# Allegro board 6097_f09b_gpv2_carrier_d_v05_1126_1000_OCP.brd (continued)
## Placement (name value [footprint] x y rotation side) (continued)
C584  10UF  [C0402]  178.01 81.03 270 bottom
C585  10UF  [C0402]  176.99 81.03 90 bottom
C586  10UF  [C0402]  183.64 87.53 0 bottom
C587  100UF  [C0805_H61]  196.55 47.85 180 top
C588  100UF  [C0805_H61]  191.64 99.42 270 bottom
C589  100UF  [C0805_H61]  195.7 48.81 180 bottom
C590  100UF  [C0805_H61]  193.52 99.42 270 bottom
C591  100UF  [C0805_H61]  197.82 41.91 270 top
C592  0.1UF  [C0201]  198.85 82.38 0 bottom
C593  0.1UF  [C0201]  189.59 84.68 180 bottom
C594  0.1UF  [C0201]  197.57 87.12 180 bottom
C595  0.1UF  [C0201]  197.96 88.83 270 bottom
C596  0.1UF  [C0201]  191.34 82.93 270 bottom
C597  0.1UF  [C0201]  197.03 89.02 90 bottom
C598  0.1UF  [C0201]  197.91 72.9 90 bottom
C599  0.1UF  [C0201]  197.61 74.04 180 bottom
C600  0.1UF  [C0201]  192.74 74.42 0 bottom
C601  0.1UF  [C0201]  195.62 72.14 270 bottom
C602  0.1UF  [C0201]  199.54 70 0 bottom
C603  0.1UF  [C0201]  197.9 76.83 90 bottom
C604  0.1UF  [C0201]  196.11 89.02 90 bottom
C605  0.1UF  [C0201]  192.71 86.79 0 bottom
C606  0.1UF  [C0201]  189.69 77.98 270 bottom
C607  0.1UF  [C0201]  194.66 82.3 180 bottom
C609  0.1UF  [C0201]  196.27 79.48 270 bottom
C610  0.1UF  [C0201]  191.05 80.9 90 bottom
C611  0.1UF  [C0201]  192.61 81.03 270 bottom
C612  0.1UF  [C0201]  197.38 79.98 270 bottom
C613  4.7UF  [C0402]  199.6 87.89 0 bottom
C614  100UF  [C0805_H61]  203.62 82.89 0 bottom
C615  4.7UF  [C0402]  199.6 89.66 0 bottom
C616  4.7UF  [C0402]  199.55 84.42 0 bottom
C617  4.7UF  [C0402]  199.6 86.36 0 bottom
C618  0.1UF  [C0201]  174.59 83.56 0 bottom
C619  0.1UF  [C0201]  174.59 76.56 0 bottom
C620  0.1UF  [C0201]  172.65 84.51 0 bottom
C621  0.1UF  [C0201]  170.59 83.56 0 bottom
C622  0.1UF  [C0201]  169.18 81.01 90 bottom
C623  0.1UF  [C0201]  170.16 81.01 90 bottom
C624  0.1UF  [C0201]  168.22 81.01 90 bottom
C625  0.1UF  [C0201]  172.66 83.59 180 bottom
C626  0.1UF  [C0201]  172.13 81.01 270 bottom
C627  0.1UF  [C0201]  171.59 76.49 0 bottom
C628  0.1UF  [C0201]  170.59 86.49 0 bottom
C629  0.1UF  [C0201]  171.12 81.01 90 bottom
C630  0.1UF  [C0201]  173.15 81.01 90 bottom
C631  0.1UF  [C0201]  170.59 84.49 0 bottom
C632  0.1UF  [C0201]  172.7 86.36 0 bottom
C633  0.1UF  [C0201]  171.59 75.56 0 bottom
C634  0.1UF  [C0201]  172.7 85.42 180 bottom
C635  0.1UF  [C0201]  170.59 85.56 0 bottom
C636  0.1UF  [C0201]  174.59 84.49 0 bottom
C637  0.1UF  [C0201]  174.17 81.01 270 bottom
C638  0.1UF  [C0201]  174.59 74.57 0 bottom
C639  0.1UF  [C0201]  171.59 78.49 0 bottom
C640  0.1UF  [C0201]  167.27 81.01 90 bottom
C641  0.1UF  [C0201]  174.59 77.49 0 bottom
C642  0.1UF  [C0201]  175.16 81.01 90 bottom
C643  0.1UF  [C0201]  174.59 75.49 0 bottom
C644  0.1UF  [C0201]  171.59 77.56 0 bottom
C645  4.7UF  [C0402]  163.22 76.66 180 bottom
C646  4.7UF  [C0402]  163.27 81.96 180 bottom
C647  4.7UF  [C0402]  163.27 80.94 180 bottom
C648  4.7UF  [C0402]  163.27 79.93 180 bottom
C649  4.7UF  [C0402]  163.27 78.91 180 bottom
C650  4.7UF  [C0402]  163.22 77.77 180 bottom
C651  0.1UF  [C0201]  183.62 72.19 180 bottom
C652  0.1UF  [C0201]  188.87 81.15 270 bottom
C653  0.1UF  [C0201]  183.6 89.49 180 bottom
C654  0.1UF  [C0201]  176.59 71.49 0 bottom
C655  100UF  [C0805_H61]  202.45 86.75 180 bottom
C656  0.1UF  [C0201]  176.59 89.56 0 bottom
C657  0.1UF  [C0201]  183.57 88.55 180 bottom
C658  0.1UF  [C0201]  183.62 71.25 180 bottom
C659  0.1UF  [C0201]  176.59 90.49 0 bottom
C660  0.1UF  [C0201]  176.59 70.57 0 bottom
C661  0.1UF  [C0201]  189.81 81.15 270 bottom
C662  0.1UF  [C0201]  171.61 71.98 0 bottom
C663  0.1UF  [C0201]  171.61 71.07 0 bottom
C664  0.1UF  [C0201]  171.61 70.15 0 bottom
C665  0.1UF  [C0201]  188.04 92.1 270 bottom
C666  0.1UF  [C0201]  193.32 92.05 270 bottom
C667  4.7UF  [C0402]  183.82 93.62 90 bottom
C668  4.7UF  [C0402]  183.57 91.54 180 bottom
C669  4.7UF  [C0402]  183.57 90.5 180 bottom
C670  4.7UF  [C0402]  196.68 94.19 90 bottom
C671  4.7UF  [C0402]  192.53 94.21 90 bottom
C672  4.7UF  [C0402]  194.59 94.21 90 bottom
C673  4.7UF  [C0402]  197.87 91.95 270 bottom
C674  4.7UF  [C0402]  190.6 94.21 90 bottom
C675  0.1UF  [C0201]  185.59 72.48 0 bottom
C676  0.1UF  [C0201]  191.27 91.95 270 bottom
C677  0.1UF  [C0201]  171.58 90.75 0 bottom
C678  0.1UF  [C0201]  177.39 72.77 0 bottom
C679  0.1UF  [C0201]  183.79 67.51 270 bottom
C680  0.1UF  [C0201]  185.59 71.55 0 bottom
C681  0.1UF  [C0201]  177.59 87.56 0 bottom
C682  0.1UF  [C0201]  171.61 72.89 0 bottom
C683  0.1UF  [C0201]  183.59 69.95 180 bottom
C684  0.1UF  [C0201]  171.61 73.81 0 bottom
C685  0.1UF  [C0201]  171.61 69.24 0 bottom
C686  0.1UF  [C0201]  182.29 68.82 90 bottom
C687  0.1UF  [C0201]  190.32 68.92 90 bottom
C688  0.1UF  [C0201]  179.17 68.82 90 bottom
C689  0.1UF  [C0201]  188.42 68.99 90 bottom
C690  0.1UF  [C0201]  187.48 68.99 90 bottom
C691  0.1UF  [C0201]  186.54 68.99 90 bottom
C692  0.1UF  [C0201]  185.6 68.99 90 bottom
C693  0.1UF  [C0201]  181.24 68.82 90 bottom
C694  0.1UF  [C0201]  180.21 68.82 90 bottom
C715  0.1UF  [C0201]  183.57 69.01 180 bottom
C716  0.1UF  [C0201]  196.05 67.95 270 bottom
C717  0.1UF  [C0201]  193.12 67.99 270 bottom
C718  0.1UF  [C0201]  195.14 67.92 270 bottom
C719  0.1UF  [C0201]  177.34 68.94 90 bottom
C720  0.1UF  [C0201]  176.33 68.91 90 bottom
C721  0.1UF  [C0201]  194.95 91.95 270 bottom
C722  0.1UF  [C0201]  175.29 68.91 90 bottom
C723  0.1UF  [C0201]  174.22 68.88 90 bottom
C724  0.1UF  [C0201]  173.15 68.88 90 bottom
C728  0.1UF  [C0201]  171.58 89.71 0 bottom
C729  0.1UF  [C0201]  171.55 88.57 0 bottom
C730  0.1UF  [C0201]  171.55 87.48 0 bottom
C732  0.1UF  [C0201]  190.25 90.06 270 bottom
C733  0.1UF  [C0201]  181.17 92.06 270 bottom
C734  0.1UF  [C0201]  180.01 92.06 270 bottom
C749  4.7UF  [C0402]  175.13 92.05 270 bottom
C750  4.7UF  [C0402]  173.02 92.02 270 bottom
C751  4.7UF  [C0402]  177.11 92.02 270 bottom
C752  4.7UF  [C0402]  186.97 92 270 bottom
C759  100NF  [C0402]  67.84 65.25 270 bottom
C760  1UF  [C0402]  66.83 65.25 270 bottom
C761  100NF  [C0402]  65.13 65.3 270 bottom
C762  1UF  [C0402]  64.11 65.3 270 bottom
C765  100NF  [C0402]  190.62 144.68 0 top
C769  100NF  [C0402]  59.97 57.81 0 bottom
C770  10UF  [C0402]  69.11 67.67 180 bottom
C771  100NF  [C0402]  63.7 57.2 90 bottom
C772  100NF  [C0402]  59.97 60.71 0 bottom
C773  100NF  [C0402]  67.97 57.68 180 bottom
C774  100NF  [C0402]  67.97 60.73 180 bottom
C775  100NF  [C0402]  67.97 61.75 180 bottom
C776  100NF  [C0402]  59.97 61.72 0 bottom
C806  1UF  [C0402]  76.66 26.09 0 top
C875  0.22UF  [C0402]  172.38 103.28 90 top
C876  0.22UF  [C0402]  171.3 103.27 90 top
C877  0.22UF  [C0402]  170.29 103.27 90 top
C878  0.22UF  [C0402]  160.29 100.25 180 top
C879  0.22UF  [C0402]  160.29 99.23 180 top
C880  0.22UF  [C0402]  190.73 103.13 90 bottom
C881  0.22UF  [C0402]  189.71 103.13 90 bottom
C882  0.22UF  [C0402]  189.14 105.14 90 bottom
C883  0.22UF  [C0402]  188.12 105.14 90 bottom
C884  0.22UF  [C0402]  187.49 103.18 90 bottom
C885  0.22UF  [C0402]  186.47 103.18 90 bottom
C886  0.22UF  [C0402]  185.76 105.1 90 bottom
C887  0.22UF  [C0402]  184.75 105.1 90 bottom
C888  0.22UF  [C0402]  183.98 101.55 90 bottom
C889  0.22UF  [C0402]  182.96 101.55 90 bottom
C890  0.22UF  [C0402]  181.49 102.84 90 bottom
C891  0.22UF  [C0402]  180.47 102.84 90 bottom
C892  0.22UF  [C0402]  178.97 104.98 90 bottom
C893  0.22UF  [C0402]  177.96 104.98 90 bottom
C894  0.22UF  [C0402]  175.18 103.72 90 bottom
C895  0.22UF  [C0402]  174.17 103.72 90 bottom
C896  0.22UF  [C0402]  184.22 103.38 90 top
C897  0.22UF  [C0402]  183.21 103.38 90 top
C898  0.22UF  [C0402]  182.01 103.36 90 top
C899  0.22UF  [C0402]  181 103.36 90 top
C900  0.22UF  [C0402]  179.78 103.38 90 top
C901  0.22UF  [C0402]  178.77 103.38 90 top
C902  0.22UF  [C0402]  177.55 103.34 90 top
C903  0.22UF  [C0402]  176.54 103.34 90 top
C904  0.22UF  [C0402]  175.48 103.3 90 top
C905  0.22UF  [C0402]  174.46 103.3 90 top
C906  0.22UF  [C0402]  173.4 103.28 90 top
C909  100NF  [C0402]  65.5 20.99 90 top
C910  100NF  [C0402]  66.52 20.99 90 top
C912  0.01UF  [C0402]  202.72 76.02 0 bottom
C913  0.01UF  [C0402]  202.72 75 0 bottom
C948  10UF  [C0805_H61]  194.05 3.43 0 bottom
C949  100NF  [C0402]  193.6 4.89 0 bottom
C950  100NF  [C0402]  183.92 119.48 0 top
C951  0.01UF  [C0402]  183.92 118.47 0 top
C952  100NF  [C0402]  89.2 39 180 top
C953  100NF  [C0402]  122.42 38.25 0 bottom
C954  12PF  [C0402]  112.3 40.43 90 top
C955  12PF  [C0402]  112.32 36.75 270 top
C959  1UF  [C0402]  122.42 39.3 180 bottom
C960  1UF  [C0402]  119.22 36.09 90 bottom
C961  1UF  [C0402]  118.17 36.04 90 bottom
C964  1UF  [C0402]  115.37 41.22 180 top
C965  1UF  [C0402]  122.42 37.19 180 bottom
C966  1UF  [C0402]  121.6 35.79 90 bottom
C967  1UF  [C0402]  120.54 36.04 90 bottom
C968  1UF  [C0402]  119.95 44.15 90 top
C969  22UF  [C0805_H61]  124.36 34.37 0 top
C970  0.01UF  [C0402]  121.95 33.53 270 top
C971  0.01UF  [C0402]  120.93 33.53 270 top
C972  1UF  [C0402]  115.67 37.47 270 top
C973  1UF  [C0402]  116.48 33.53 270 top
C974  1UF  [C0402]  117.5 33.53 270 top
C975  100NF  [C0402]  68.66 26.97 0 top
C1010  0.22UF  [C0402]  151.68 58.85 180 top
C1011  0.22UF  [C0402]  153.51 58.51 180 top
C1012  0.22UF  [C0402]  153.51 57.49 180 top
C1013  0.22UF  [C0402]  151.69 57.18 180 top
C1014  0.22UF  [C0402]  151.69 56.16 180 top
C1015  0.22UF  [C0402]  153.51 77.43 180 top
C1016  0.22UF  [C0402]  153.48 76.36 180 top
C1017  0.22UF  [C0402]  151.68 76.09 180 top
C1018  0.22UF  [C0402]  151.68 75.07 180 top
C1019  0.22UF  [C0402]  153.51 74.73 180 top
C1020  0.22UF  [C0402]  153.51 73.71 180 top
C1021  0.22UF  [C0402]  151.68 73.38 180 top
C1022  0.22UF  [C0402]  151.68 72.37 180 top
C1023  0.22UF  [C0402]  153.51 72.02 180 top
C1024  0.22UF  [C0402]  153.51 71.01 180 top
C1025  0.22UF  [C0402]  151.68 70.68 180 top
C1026  0.22UF  [C0402]  151.68 69.67 180 top
C1027  0.22UF  [C0402]  153.51 69.32 180 top
C1028  0.22UF  [C0402]  153.51 68.3 180 top
C1029  0.22UF  [C0402]  151.68 67.98 180 top
C1030  0.22UF  [C0402]  151.68 66.96 180 top
C1031  0.22UF  [C0402]  153.51 66.62 180 top
C1032  0.22UF  [C0402]  153.51 65.6 180 top
C1033  0.22UF  [C0402]  151.68 65.27 180 top
C1034  0.22UF  [C0402]  151.68 64.26 180 top
C1035  0.22UF  [C0402]  153.51 63.91 180 top
C1036  0.22UF  [C0402]  153.51 62.9 180 top
C1037  0.22UF  [C0402]  151.68 62.57 180 top
C1038  0.22UF  [C0402]  151.68 61.56 180 top
C1039  0.22UF  [C0402]  153.51 61.21 180 top
C1040  0.22UF  [C0402]  153.51 60.19 180 top
C1041  0.22UF  [C0402]  151.68 59.87 180 top
C1058  0.22UF  [C0402]  158.51 55.35 270 top
C1059  0.22UF  [C0402]  159.53 55.35 270 top
C1060  0.22UF  [C0402]  160.67 55.3 270 top
C1061  0.22UF  [C0402]  161.69 55.3 270 top
C1062  0.22UF  [C0402]  162.81 55.33 270 top
C1063  0.22UF  [C0402]  163.82 55.33 270 top
C1064  0.22UF  [C0402]  172.03 55.76 270 top
C1065  0.22UF  [C0402]  173.04 55.76 270 top
C1066  0.22UF  [C0402]  174.16 55.76 270 top
C1067  0.22UF  [C0402]  175.18 55.76 270 top
C1068  0.22UF  [C0402]  176.37 55.76 270 top
C1069  0.22UF  [C0402]  177.39 55.76 270 top
C1070  0.22UF  [C0402]  178.48 55.76 270 top
C1071  0.22UF  [C0402]  179.49 55.76 270 top
C1072  0.22UF  [C0402]  156.35 55.35 270 top
C1073  0.22UF  [C0402]  157.37 55.35 270 top
C1074  100NF  [C0402]  183.57 132.73 0 bottom
C1075  100NF  [C0402]  183.65 136.57 180 bottom
C1078  100NF  [C0402]  130.48 42.88 180 bottom
C1079  100NF  [C0402]  139.34 43 0 bottom
C1082  100NF  [C0402]  181.84 124.04 0 bottom
C1083  100NF  [C0402]  24.61 96.85 0 bottom
C1085  100NF  [C0402]  36.28 119.39 180 top
C1086  100NF  [C0402]  32.15 116.08 90 top
C1087  100NF  [C0402]  63.77 119.28 0 top
C1088  100NF  [C0402]  56.81 116.26 90 top
C1089  100NF  [C0402]  87.05 119.89 0 top
C1090  100NF  [C0402]  81.57 115.35 90 top
C1091  100NF  [C0402]  111.43 118.75 180 top
C1092  100NF  [C0402]  106.83 115.45 90 top
C1093  100NF  [C0402]  135.33 118.88 180 top
C1094  100NF  [C0402]  130.74 115.58 90 top
C1095  100NF  [C0402]  161.85 125.92 90 top
C1096  100NF  [C0402]  159.25 115.98 90 top
C1097  100NF  [C0402]  21.43 111.92 180 bottom
C1098  100NF  [C0402]  30.05 116.59 90 bottom
C1099  100NF  [C0402]  46.68 109.96 270 bottom
C1100  100NF  [C0402]  53.4 115.17 90 bottom
C1101  100NF  [C0402]  73.75 108.72 270 bottom
C1102  100NF  [C0402]  78.12 114.47 90 bottom
C1103  100NF  [C0402]  97.13 109.04 270 bottom
C1104  100NF  [C0402]  103.46 114.5 90 bottom
C1105  100NF  [C0402]  120.36 109.36 270 bottom
C1106  100NF  [C0402]  127.31 114.96 90 bottom
C1107  100NF  [C0402]  148.16 112.43 270 bottom
C1108  100NF  [C0402]  154.89 118.13 90 bottom
C1111  1000PF  [C0402]  52.52 29.51 270 bottom
C1112  1000PF  [C0402]  46.85 29.51 270 bottom
C1113  1000PF  [C0402]  55.78 29.51 270 bottom
C1114  22UF  [C0805_H61]  114.15 34.82 180 top
C1115  100NF  [C0402]  41.53 44.53 180 bottom
C1116  100NF  [C0402]  37.26 47.93 90 bottom
C1117  100NF  [C0402]  36.22 48.62 90 bottom
C1118  100NF  [C0402]  39.75 45.95 270 bottom
C1119  100NF  [C0402]  36.22 51.26 270 bottom
C1120  100NF  [C0402]  37.29 51.29 270 bottom
C1121  1UF  [C0402]  35.16 51.29 270 bottom
C1122  1UF  [C0402]  49.71 41.88 180 bottom
C1123  0.01UF  [C0402]  41.99 45.97 90 bottom
C1124  0.01UF  [C0402]  40.79 45.95 270 bottom
C1125  100NF  [C0402]  37.01 44.55 180 bottom
C1126  0.01UF  [C0402]  37.01 43.36 180 bottom
C1127  1UF  [C0402]  42.44 41.02 270 bottom
C1128  2.2UF  [C0603]  43.62 40.65 270 bottom
C1129  1UF  [C0402]  45.75 43.99 90 bottom
C1130  100NF  [C0402]  47.12 43.99 90 bottom
C1131  100NF  [C0402]  29.71 35.53 270 top
C1132  22UF  [C0805_H61]  27.89 37.03 270 top
C1133  2.2UF  [C0603]  29.94 33.8 180 top
C1134  1UF  [C0402]  22.25 80.11 270 top
C1135  100NF  [C0402]  31.32 71.55 0 bottom
C1136  100NF  [C0402]  31.29 66.7 0 bottom
C1137  1UF  [C0402]  30.86 76.22 270 top
C1138  100NF  [C0402]  25.02 37.07 180 bottom
C1139  100NF  [C0402]  38.58 66.62 0 bottom
C1140  1UF  [C0402]  38.18 76.2 270 top
C1141  100NF  [C0402]  38.58 71.58 0 bottom
C1142  100NF  [C0402]  22.35 70.48 180 bottom
C1143  1UF  [C0402]  24.54 40.64 90 top
C1144  100NF  [C0402]  22.15 75.46 180 bottom
C1145  100NF  [C0402]  30.91 85.9 0 bottom
C1146  1UF  [C0402]  45.77 76.2 270 top
C1147  100NF  [C0402]  30.02 90.75 180 bottom
C1148  100NF  [C0402]  24.92 31.06 0 bottom
C1149  1UF  [C0402]  30.38 95.43 270 top
C1151  100NF  [C0402]  124.52 144.63 90 top
C1152  0.01UF  [C0402]  123.36 144.62 90 top
C1153  22UF  [C0805_H61]  125.98 143.76 90 top
C1154  1UF  [C0402]  45.72 42.14 270 bottom
C1155  0.01UF  [C0402]  47.19 42.14 270 bottom
C1156  100NF  [C0402]  51.59 45.54 90 top
C1157  100NF  [C0402]  54.76 43.89 0 top
C1158  47PF  [C0402]  51.59 45.54 90 bottom
C1159  47PF  [C0402]  52.58 47.32 270 top
C1160  1UF  [C0402]  13.76 55.25 90 top
C1161  100NF  [C0402]  13.95 49.51 180 top
C1162  1UF  [C0402]  20.56 46.43 0 top
C1163  100NF  [C0402]  17.94 49.47 0 top
C1164  100NF  [C0402]  15.98 50.69 90 top
C1165  100NF  [C0402]  22.94 59.93 180 top
C1166  100NF  [C0402]  19.09 54.38 0 top
C1167  100NF  [C0402]  8.21 45.18 90 top
C1168  100NF  [C0402]  8.15 59.05 270 top
C1169  100NF  [C0402]  22.93 44.36 180 top
C1170  100NF  [C0402]  8.05 36.35 0 top
C1171  10UF  [C0603]  8.15 35.13 0 top
C1172  22UF  [C0805_H61]  114.15 32.84 180 top
C1173  22UF  [C0805_H61]  119.15 32.59 270 top
C1174  100NF  [C0402]  186.34 131.46 180 top
C1175  0.01UF  [C0402]  186.33 132.54 180 top
C1176  22UF  [C0805_H61]  185.53 129.84 180 top
C1177  100NF  [C0402]  48.27 42.14 270 bottom
C1178  1000PF  [C0402]  73.89 33.55 270 bottom
C1179  1000PF  [C0402]  69.82 33.55 270 bottom
C1180  100NF  [C0402]  4.55 74.5 270 top
C1181  100NF  [C0402]  3.63 88.56 0 bottom
C1182  100NF  [C0402]  3.61 82.05 0 bottom
C1183  100NF  [C0402]  3.6 85.22 0 bottom
C1184  100NF  [C0402]  3.73 95.83 0 bottom
C1185  100NF  [C0402]  3.67 91.72 0 bottom
C1186  100NF  [C0402]  79.95 46.35 270 bottom
C1187  1UF  [C0402]  80.98 46.35 270 bottom
C1189  100NF  [C0402]  10.31 47.15 270 top
C1191  100NF  [C0402]  19.83 48.15 180 top
C1192  100NF  [C0402]  17.59 55.2 90 top
C1193  100NF  [C0402]  12.8 52.02 180 top
C1194  100NF  [C0402]  17.41 51.91 180 top
C1195  100NF  [C0402]  9.72 56.71 180 top
C1196  100NF  [C0402]  21.74 56.77 90 top
C1197  100NF  [C0402]  19.1 56.66 270 top
C1198  100NF  [C0402]  19.2 51.91 0 top
C1199  100NF  [C0402]  14.6 52.03 0 top
C1200  100NF  [C0402]  15.94 53.54 270 top
C1201  100NF  [C0402]  10.95 57.78 180 top
C1202  100NF  [C0402]  190.73 118.67 270 bottom
C1203  100NF  [C0402]  193.55 116.56 180 bottom
C1204  100NF  [C0402]  98.53 61.11 0 bottom
C1205  100NF  [C0402]  34.16 89.56 90 bottom
C1206  22UF  [C0805_H61]  44.76 111.35 180 top
C1207  22UF  [C0805_H61]  118.7 110.81 180 top
C1208  22UF  [C0805_H61]  69.86 108.95 180 top
C1209  22UF  [C0805_H61]  94.82 109.88 180 top
C1210  22UF  [C0805_H61]  19.76 111.4 180 top
C1211  22UF  [C0805_H61]  144.3 111.71 180 top
C1212  22UF  [C0805_H61]  90.8 109.86 0 bottom
C1213  22UF  [C0805_H61]  65.88 110.85 0 bottom
C1214  22UF  [C0805_H61]  167.53 113.32 0 bottom
C1215  22UF  [C0805_H61]  42.56 111.74 0 bottom
C1216  22UF  [C0805_H61]  115.2 109.18 0 bottom
C1217  22UF  [C0805_H61]  140.33 110.63 0 bottom
C1218  100NF  [C0402]  3.12 40.36 90 bottom
C1219  100NF  [C0402]  1.55 40.44 270 bottom
C1220  100NF  [C0402]  5.54 39.93 0 bottom
C1221  100NF  [C0402]  7.39 39.93 0 bottom
C1222  100NF  [C0402]  205.84 73.97 180 top
C1223  1UF  [C0402]  183.64 135.54 0 bottom
C1224  100NF  [C0402]  1.61 102.83 90 bottom
C1225  100NF  [C0402]  3.98 107.94 180 bottom
C1226  100NF  [C0402]  140.5 38.65 0 top
C1227  100NF  [C0402]  131.79 38.19 180 top
C1228  1000PF  [C0402]  72.38 31.02 180 top
C1229  100PF  [C0201]  16.79 91.29 270 top
C1230  100PF  [C0201]  19.18 18.41 0 top
C1231  100PF  [C0201]  197.39 32.53 270 top
C1232  100NF  [C0402]  57.45 14.36 270 bottom
C1233  100NF  [C0402]  33.51 34.3 90 top
C1234  100NF  [C0402]  34.12 22.26 0 top
C1235  1UF  [C0402]  31.77 32.38 90 bottom
C1236  100PF  [C0201]  185.22 103.29 270 top
C1237  1UF  [C0402]  23.63 118.56 180 top
C1238  1UF  [C0402]  47.73 118.17 180 top
C1239  1UF  [C0402]  73.32 117.08 180 top
C1240  1UF  [C0402]  98.76 117.86 180 top
C1241  1UF  [C0402]  122.62 117.99 180 top
C1242  1UF  [C0402]  144.15 116.54 180 top
C1243  1UF  [C0402]  162.66 120.37 0 bottom
C1244  1UF  [C0402]  134.79 117.46 0 bottom
C1245  1UF  [C0402]  110.87 116.99 0 bottom
C1246  1UF  [C0402]  85.5 116.91 0 bottom
C1247  1UF  [C0402]  61.13 116.88 0 bottom
C1248  1UF  [C0402]  39.02 119.33 0 bottom
C1249  100PF  [C0201]  178.82 114.68 180 bottom
C1250  100PF  [C0201]  180.63 115.31 180 bottom
C1251  100PF  [C0201]  182.89 117.07 180 bottom
C1252  100PF  [C0201]  24.35 2.72 180 bottom
D1  LED BLUE  [LED_LTSTS270KSKT]  100.26 146.94 0 bottom
D3  LED_GREEN  [LED_1921]  208.1 108.05 270 top
D4  PCA9517ADP  [TSSOP8_3]  134.9 41.99 180 bottom
D5  LED BLUE  [LED_LTSTS270KSKT]  104.23 146.94 0 bottom
D17  LED_YEL/GRE  [LED_16213XA]  40.16 58.39 180 top
D18  SDMK0340L-7-F  [SOD323]  9.3 33.35 180 top
DM10  PCIE_SWITCH_FLASH  [TP30_FOR_BOM]  -14.81 16.41 270 top
H1  -  [HOLE_D3-1N]  198.84 104.77 0 top
H2  -  [HOLE_D3-1N]  167.34 55.77 0 top
H3  GNDHOLE_8PIN  [GND_C10D4B10]  202.5 116 0 top
H4  GNDHOLE_8PIN  [GND_C10D4B10]  7.5 116 0 top
H5  GNDHOLE_8PIN  [GND_C10D4B10]  202.5 19 0 top
H6  GNDHOLE_8PIN  [GND_C10D4B10]  7.5 19 0 top
H7  -  [HOLE_OB6X7-6OBD3-2X4-8TN_NPM]  62.43 27.25 0 top
H8  -  [HOLE_OB6X7-6OBD3-2X4-8TN_NPM]  110.43 27.25 0 top
H9  -  [HOLE_OB6X7-6OBD3-2X4-8TN_NPM]  86.43 27.25 0 top
H10  -  [HOLE_OB6X7-6OBD3-2X4-8TN_NPM]  134.43 27.25 0 top
H11  -  [HOLE_OB6X7-6OBD3-2X4-8TN_NPM]  38.43 27.25 0 top
H12  -  [HOLE_OB6X7-6OBD3-2X4-8TN_NPM]  158.43 27.25 0 top
H13  -  [HOLE_OB6X7-6OBD3-2X4-8BN_NPM]  76.68 20 0 top
H14  -  [HOLE_OB6X7-6OBD3-2X4-8BN_NPM]  52.68 20 0 top
H15  -  [HOLE_OB6X7-6OBD3-2X4-8BN_NPM]  28.68 20 0 top
H16  -  [HOLE_OB6X7-6OBD3-2X4-8BN_NPM]  100.68 20 0 top
H17  -  [HOLE_OB6X7-6OBD3-2X4-8BN_NPM]  124.68 20 0 top
H18  -  [HOLE_OB6X7-6OBD3-2X4-8BN_NPM]  148.68 20 0 top
H19  -  [HOLE_D2-15N_PLTB3]  62.43 21.25 0 top
H20  -  [HOLE_D2-15N_PLTB3]  38.43 21.25 0 top
H21  -  [HOLE_D2-15N_PLTB3]  86.43 21.25 0 top
H22  -  [HOLE_D2-15N_PLTB3]  110.43 21.25 0 top
H23  -  [HOLE_D2-15N_PLTB3]  134.43 21.25 0 top
H24  -  [HOLE_D2-15N_PLTB3]  158.43 21.25 0 top
H25  -  [HOLE_D2-15N_PLTB3]  28.68 14 0 top
H26  -  [HOLE_D2-15N_PLTB3]  148.68 14 0 top
H27  -  [HOLE_D2-15N_PLTB3]  124.68 14 0 top
H28  -  [HOLE_D2-15N_PLTB3]  76.68 14 0 top
H29  -  [HOLE_D2-15N_PLTB3]  52.68 14 0 top
H30  -  [HOLE_D2-15N_PLTB3]  100.68 14 0 top
H31  GNDHOLE_8PIN  [GND_C10D4B10]  90.5 8.5 0 top
H32  -  [HOLE_C7D2-7B3_NPB]  40.68 143.5 0 top
H33  -  [HOLE_C7D2-7B3_NPB]  88.68 143.5 0 top
H34  -  [HOLE_C7D2-7B3_NPB]  136.68 143.5 0 top
H35  -  [HOLE_C7D2-7B3_NPB]  176.98 4 0 top
H36  -  [HOLE_C7D2-7B3_NPB]  16.48 4 0 top
J4  SCONN134_MDT670M01005  [CON_F134S2H4D4S_P0-5W7-55_LUVXA]  40.68 129.73 90 top
J6  SCONN134_MDT670M01005  [CON_F134S2H4D4S_P0-5W7-55_LUVXA]  50.42 136.98 90 bottom
J8  SCONN134_MDT670M01005  [CON_F134S2H4D4S_P0-5W7-55_LUVXA]  146.42 136.98 90 bottom
J9  DELTA-L  [TRIANG_LAUNCH_3PXA]  124.56 158.45 270 top
J10  DELTA-L  [TRIANG_LAUNCH_3PXA]  266.68 156.07 90 bottom
J11  DELTA-L  [TRIANG_LAUNCH_3PXA]  304.35 158.61 90 top
J12  DELTA-L  [TRIANG_LAUNCH_3PXA]  160.09 158.46 90 top
J13  DELTA-L  [TRIANG_LAUNCH_3PXA]  304.35 156.06 270 bottom
J14  DELTA-L  [TRIANG_LAUNCH_3PXA]  266.68 158.6 270 top
J15  DELTA-L  [TRIANG_LAUNCH_3PXA]  80.32 157.82 90 top
J16  DELTA-L  [TRIANG_LAUNCH_3PXA]  245.52 155.91 270 bottom
J17  DELTA-L  [TRIANG_LAUNCH_3PXA]  245.52 158.46 90 top
J18  DELTA-L  [TRIANG_LAUNCH_3PXA]  20.68 157.82 270 top
J19  DELTA-L  [TRIANG_LAUNCH_3PXA]  192.47 155.92 90 bottom
J20  DELTA-L  [TRIANG_LAUNCH_3PXA]  192.47 158.45 270 top
J24  -  [TDR_3P_C85P67_141_100M_Q]  117.82 -161.52 270 bottom
J25  -  [TDR_3P_C85P67_141_100M_Q]  117.82 -168.15 270 bottom
J26  -  [TDR_3P_C85P67_141_100M_Q]  25.26 -168.29 270 top
J34  SCONN134_MDT670M01005  [CON_F134S2H4D4S_P0-5W7-55_LUVXA]  98.42 136.98 90 bottom
J36  SCONN134_MDT670M01005  [CON_F134S2H4D4S_P0-5W7-55_LUVXA]  88.68 129.73 90 top
J38  SCONN134_MDT670M01005  [CON_F134S2H4D4S_P0-5W7-55_LUVXA]  136.68 129.73 90 top
J41  SCONN120_61083-12250QLF  [CON_120S2H2D_P0-8W4-4_LUV_H237]  56.1 6.55 90 bottom
J46  CONN2_G2100HT0038-066-H  [HEADER1X2XJ_H339]  208.01 54 0 top
J47  SCONN8_51530-00801-V01  [CON_8S1H2S_P0-5XC]  3.56 103.39 0 top
J49  SCONN160_61083-16250QLF  [CON_M160S2H2D_P0-8W4-4_LUV]  135.3 6.55 90 bottom
J50  -  [TDR_3P_C85P67_141_100M_Q]  25.26 -161.56 270 top
J51  DELTA-L  [TRIANG_LAUNCH_3PXA]  124.56 155.92 90 bottom
J52  DELTA-L  [TRIANG_LAUNCH_3PXA]  160.09 155.91 270 bottom
J53  DELTA-L  [TRIANG_LAUNCH_3PXA]  80.32 155.27 270 bottom
J54  DELTA-L  [TRIANG_LAUNCH_3PXA]  20.68 155.28 90 bottom
J55  SCONN5_47590-0001  [USB1XBD]  117 146.4 90 top
J56  SCONN4_50228-0047N-001_F09  [CON_4S1H2S_P1XA_F09]  2.9 29.77 180 top
J58  SCONN8_50228-00871-001_F09  [CON_8S1H2S_P1XD_CAP_F09]  2.95 39.95 180 top
J59  CONN2_G2100HT0038-066-H  [HEADER1X2XJ_H339]  3.84 4.27 180 top
J60  SCONN5_105133-0011  [USB1XAY]  190.68 133.63 90 top
L6  330/3A  [L0805]  68.38 69.77 0 bottom
L7  10UH  [L1007]  203.48 80.37 180 bottom
L8  10UH  [L_CMLE053T_4-85X4-7]  203.24 91.55 270 bottom
L11  BLM15PX471SN1D  [L0402]  114.2 31.27 0 top
L13  BLM15PX471SN1D  [L0402]  114.63 37.46 90 top
L14  BLM15PX121SN1D  [L0402]  30.81 35.51 270 top
NOREF  -  []  194.5 142.01 90 top
NOREF#2  -  []  7.5 116 0 top
NOREF#3  -  []  127.1 111.79 90 top
NOREF#4  -  []  50.15 114.71 0 top
NOREF#5  -  []  161 116.33 0 top
NOREF#6  -  []  90.5 8.5 0 top
NOREF#7  -  []  28.68 20 0 top
NOREF#8  -  []  137.55 144.53 0 top
NOREF#9  -  []  119.13 113.91 0 top
NOREF#10  -  []  194.24 -125.95 0 top
NOREF#11  -  []  76.68 20 0 top
NOREF#12  -  []  48.27 114.17 0 top
NOREF#13  -  []  71.42 133.22 0 top
NOREF#14  -  []  202.5 116 0 top
NOREF#15  -  []  483.89 -39.84 0 top
NOREF#16  -  []  72.88 112.98 90 top
NOREF#17  -  []  52.68 20 0 top
NOREF#18  -  []  158.82 116.53 90 top
NOREF#19  -  []  67.43 133.53 0 top
NOREF#20  -  []  75.03 113.31 0 top
NOREF#21  -  []  23.56 114.57 0 top
NOREF#22  -  []  100.68 20 0 top
NOREF#23  -  []  169.92 144.27 0 top
NOREF#24  -  []  122.23 113.91 90 top
NOREF#25  -  []  7.5 19 0 top
NOREF#26  -  []  157.95 124.4 90 top
NOREF#27  -  []  202.5 19 0 top
NOREF#28  -  []  17.05 7.45 0 top
NOREF#29  -  []  77.63 111.3 90 top
NOREF#30  -  []  157.01 149 0 top
NOREF#31  -  []  75.03 111.51 90 top
NOREF#32  -  []  18.33 132.75 0 top
NOREF#33  -  []  18.42 350.5 0 top
NOREF#34  -  []  75.47 186.53 0 top
NOREF#35  -  []  95.18 113.77 0 top
NOREF#36  -  []  61.95 124.4 90 top
NOREF#37  -  []  23.26 114.45 90 top
NOREF#38  -  []  110.43 27.25 0 top
NOREF#39  -  []  157.68 125.98 90 top
NOREF#40  -  []  211 67.77 270 top
NOREF#41  -  []  369.01 149 0 top
NOREF#42  -  []  27.47 186.53 0 top
NOREF#43  -  [unnamed#2]  157.6 34.84 0 top
NOREF#44  -  []  62.43 27.25 0 top
NOREF#45  -  []  296.63 -1 0 top
NOREF#46  -  []  57.42 133.22 0 top
NOREF#47  -  []  44.87 114.04 0 top
NOREF#48  -  []  41.25 146.95 0 top
NOREF#49  -  []  211 -16.43 90 top
NOREF#50  -  []  167.42 133.23 0 top
NOREF#51  -  []  108.58 131.23 0 top
NOREF#52  -  []  211 39.83 270 top
NOREF#53  -  []  84.63 -1 0 top
NOREF#54  -  []  125.15 131.65 90 top
NOREF#55  -  []  137.05 144.95 0 top
NOREF#56  -  [unnamed#2]  56.05 8.53 0 top
NOREF#57  -  []  285.19 149 0 top
NOREF#58  -  []  98.58 113.9 0 top
NOREF#59  -  []  479.43 -3.3 0 top
NOREF#60  -  []  115.43 133.53 0 top
NOREF#61  -  []  160.7 116.2 0 top
NOREF#62  -  []  108.58 131.23 0 top
NOREF#63  -  []  168.42 135.5 0 top
NOREF#64  -  []  150.12 113.44 0 top
NOREF#65  -  []  81.93 113.15 90 top
NOREF#66  -  []  115.68 125.98 0 top
NOREF#67  -  []  0 0 0 top
NOREF#68  -  []  177.35 5.45 0 top
NOREF#69  -  []  19.68 125.98 0 top
NOREF#70  -  []  123.47 186.53 0 top
NOREF#71  -  []  202.5 19 0 top
NOREF#72  -  []  551.77 -141.13 0 top
NOREF#73  -  []  240.75 -1 0 top
NOREF#74  -  []  77.63 113.1 0 top
NOREF#75  -  []  126.87 114.26 90 top
NOREF#76  -  []  0 147.59 270 top
NOREF#77  -  []  39.79 115.19 90 top
NOREF#78  -  []  12.58 131.23 0 top
NOREF#79  -  []  134.43 27.25 0 top
NOREF#80  -  []  0 -185.17 0 top
NOREF#81  -  []  38.43 27.25 0 top
NOREF#82  -  [unnamed#2]  149.86 141.64 0 top
NOREF#83  -  []  41.05 144.95 0 top
NOREF#84  -  []  103.28 113.13 0 top
NOREF#85  -  []  23.56 114.57 0 top
NOREF#86  -  []  68.22 138.47 0 top
NOREF#87  -  []  0 0 0 top
NOREF#88  -  []  73.18 113.1 0 top
NOREF#89  -  []  192.72 -149.58 0 top
NOREF#90  -  []  203.14 -1 0 top
NOREF#91  -  []  103.28 111.33 90 top
NOREF#92  -  []  132.96 113.35 0 top
NOREF#93  -  []  53.5 112 90 top
NOREF#94  -  []  112.21 112.85 90 top
NOREF#95  -  []  140.51 -151 0 top
NOREF#96  -  []  163.8 116.2 90 top
NOREF#97  -  []  16.85 5.45 0 top
NOREF#98  -  []  153.42 133.23 0 top
NOREF#99  -  []  25.41 114.38 0 top
NOREF#100  -  []  1.21 98.89 90 top
NOREF#101  -  []  89.05 144.95 0 top
NOREF#102  -  []  67.68 125.98 0 top
NOREF#103  -  []  59.58 112.88 0 top
NOREF#104  -  []  111.91 112.98 90 top
NOREF#105  -  []  0 0 0 top
NOREF#106  -  []  127.1 113.59 0 top
NOREF#107  -  []  0 0 0 top
NOREF#108  -  []  18.68 128.25 0 top
NOREF#109  -  []  98.58 113.9 0 top
NOREF#110  -  []  2.96 106.84 0 top
NOREF#111  -  []  0 -164.57 270 top
NOREF#112  -  []  62.08 112.88 90 top
NOREF#113  -  []  146.72 113.31 0 top
NOREF#114  -  []  25.41 112.58 90 top
NOREF#115  -  []  47.97 114.04 90 top
NOREF#116  -  []  100.44 112.22 90 top
NOREF#117  -  []  96.42 135.5 0 top
NOREF#118  -  []  17.35 5.03 0 top
NOREF#119  -  []  68.92 133.22 0 top
NOREF#120  -  []  20.16 114.45 0 top
NOREF#121  -  []  30.32 113.11 90 top
NOREF#122  -  []  28.75 -1 0 top
NOREF#123  -  []  69.68 125.98 0 top
NOREF#124  -  []  2.96 99.94 90 top
NOREF#125  -  []  66.68 128.25 0 top
NOREF#126  -  []  120.42 135.5 0 top
NOREF#127  -  []  102.94 114.07 90 top
NOREF#128  -  []  16.03 -126.21 0 top
NOREF#129  -  []  39.49 115.31 90 top
NOREF#130  -  []  60.58 131.23 0 top
NOREF#131  -  []  77.53 113.37 90 top
NOREF#132  -  []  41.55 144.53 0 top
NOREF#133  -  []  114.33 132.75 0 top
NOREF#134  -  []  27.91 114.43 90 top
NOREF#135  -  []  62.38 112.76 90 top
NOREF#136  -  []  422 147.59 270 top
NOREF#137  -  []  125.42 133.23 90 top
NOREF#138  -  []  208.7 -125.37 0 top
NOREF#139  -  []  211 -97.71 90 top
NOREF#140  -  []  73.18 113.1 0 top
NOREF#141  -  []  53.42 133.22 90 top
NOREF#142  -  []  30.32 114.91 0 top
NOREF#143  -  []  59.28 112.76 0 top
NOREF#144  -  []  122.53 114.03 0 top
NOREF#145  -  []  237.08 -171.16 90 top
NOREF#146  -  []  492.29 -140.39 0 top
NOREF#147  -  []  158.43 27.25 0 top
NOREF#148  -  []  133.26 113.47 0 top
NOREF#149  -  []  109.41 112.98 0 top
NOREF#150  -  []  100.44 114.02 0 top
NOREF#151  -  []  98.28 113.77 90 top
NOREF#152  -  []  1.21 107.89 0 top
NOREF#153  -  []  61.58 112.88 0 top
NOREF#154  -  []  148.68 20 0 top
NOREF#155  -  []  135.76 113.47 90 top
NOREF#156  -  []  98.58 113.9 90 top
NOREF#157  -  []  112.57 -1 0 top
NOREF#158  -  []  268.69 -1 0 top
NOREF#159  -  []  164.92 133.23 0 top
NOREF#160  -  []  136.06 113.35 90 top
NOREF#161  -  []  105.42 133.23 0 top
NOREF#162  -  []  324.57 -1 0 top
NOREF#163  -  []  77.42 133.23 90 top
NOREF#164  -  []  227.5 136.01 90 top
NOREF#165  -  []  109.68 125.98 90 top
NOREF#166  -  []  89.25 146.95 0 top
NOREF#167  -  []  79.55 -151 0 top
NOREF#168  -  []  61.68 125.98 90 top
NOREF#169  -  []  89.55 144.53 0 top
NOREF#170  -  []  69.78 112.98 0 top
NOREF#171  -  []  163 116.33 0 top
NOREF#172  -  []  73.19 149 0 top
NOREF#173  -  []  0.61 -2.57 0 top
NOREF#174  -  []  56.69 -151 0 top
NOREF#175  -  []  149.82 113.31 90 top
NOREF#176  -  []  131.4 113.64 90 top
NOREF#177  -  []  594.33 -40.4 0 top
NOREF#178  -  []  135.26 113.47 0 top
NOREF#179  -  []  77.15 131.65 90 top
NOREF#180  -  []  90.5 8.5 0 top
NOREF#181  -  []  2 -172.57 90 top
NOREF#182  -  []  211 95.71 270 top
NOREF#183  -  []  50.15 112.91 90 top
NOREF#184  -  []  116.22 138.48 0 top
NOREF#185  -  []  48.42 135.5 0 top
NOREF#186  -  []  152.05 112.73 90 top
NOREF#187  -  []  101.42 133.23 90 top
NOREF#188  -  []  66.33 132.75 0 top
NOREF#189  -  []  36.69 115.19 0 top
NOREF#190  -  []  415.14 -1 0 top
NOREF#191  -  []  23.56 114.57 90 top
NOREF#192  -  []  36.99 115.31 0 top
NOREF#193  -  []  114.68 128.25 0 top
NOREF#194  -  []  124.37 114.21 0 top
NOREF#195  -  []  158.43 27.25 0 top
NOREF#196  -  []  177.85 5.03 0 top
NOREF#197  -  []  109.95 124.4 90 top
NOREF#198  -  []  73.18 113.1 90 top
NOREF#199  -  []  651.58 -40.58 0 top
NOREF#200  -  []  177.55 7.45 0 top
NOREF#201  -  []  202.5 116 0 top
NOREF#202  -  []  56.69 -1 0 top
NOREF#203  -  []  124.37 112.41 90 top
NOREF#204  -  []  185.36 -151 0 top
NOREF#205  -  []  211 -69.77 90 top
NOREF#206  -  []  352.51 -1 0 top
NOREF#207  -  []  154.55 114.58 90 top
NOREF#208  -  []  107.58 113.18 90 top
NOREF#209  -  []  0 2 0 top
NOREF#210  -  []  21.68 125.98 0 top
NOREF#211  -  []  211 -41.83 90 top
NOREF#212  -  []  57.8 113.85 90 top
NOREF#213  -  []  422 -164.57 270 top
NOREF#214  -  []  48.27 114.17 90 top
NOREF#215  -  []  2 0 90 top
NOREF#216  -  []  257.25 149 0 top
NOREF#217  -  []  209.73 -2.99 0 top
NOREF#218  -  []  45.25 149 0 top
NOREF#219  -  []  119.42 133.23 0 top
NOREF#220  -  []  6.14 105.14 90 top
NOREF#221  -  []  111.41 112.98 0 top
NOREF#222  -  []  122.78 -153.38 0 top
NOREF#223  -  []  7.5 116 0 top
NOREF#224  -  []  72.42 135.5 0 top
NOREF#225  -  []  150.12 113.44 90 top
NOREF#226  -  []  117.68 125.98 0 top
NOREF#227  -  []  60.58 131.23 0 top
NOREF#228  -  []  163.5 116.33 90 top
NOREF#229  -  []  86.27 112.94 90 top
NOREF#230  -  []  0.64 -124.97 0 top
NOREF#231  -  []  53.5 113.8 0 top
NOREF#232  -  [unnamed#2]  48.53 140.06 0 top
NOREF#233  -  []  86.57 112.82 90 top
NOREF#234  -  []  194.5 -136.4 90 top
NOREF#235  -  []  19.43 133.53 0 top
NOREF#236  -  []  38.99 115.31 0 top
NOREF#237  -  []  6.14 104.64 90 top
NOREF#238  -  []  17.29 -149.6 0 top
NOREF#239  -  []  211 14.43 270 top
NOREF#240  -  []  83.47 112.82 0 top
NOREF#241  -  []  164.22 138.48 0 top
NOREF#242  -  []  149.42 133.23 90 top
NOREF#243  -  []  52.65 114.76 90 top
NOREF#244  -  []  86.43 27.25 0 top
NOREF#245  -  []  116.92 133.23 0 top
NOREF#246  -  []  154.52 116.48 0 top
NOREF#247  -  []  133.68 125.98 90 top
NOREF#248  -  []  137.25 146.95 0 top
NOREF#249  -  []  122.53 114.03 0 top
NOREF#250  -  []  341.07 149 0 top
NOREF#251  -  []  85.77 112.94 0 top
NOREF#252  -  []  29.15 131.64 90 top
NOREF#253  -  []  144.42 135.5 0 top
NOREF#254  -  []  37.68 125.98 90 top
NOREF#255  -  []  122.53 114.03 90 top
NOREF#256  -  []  85.68 125.98 90 top
NOREF#257  -  []  29.42 133.22 90 top
NOREF#258  -  []  83.77 112.94 0 top
NOREF#259  -  []  150.12 113.44 0 top
NOREF#260  -  []  538.76 -42.26 0 top
NOREF#261  -  []  140.51 -1 0 top
NOREF#262  -  []  12.58 131.23 0 top
NOREF#263  -  []  6.14 101.64 90 top
NOREF#264  -  []  48.27 114.17 0 top
NOREF#265  -  []  7.5 19 0 top
NOREF#266  -  []  109.11 112.85 0 top
NOREF#267  -  []  34.62 114.96 90 top
NOREF#268  -  []  124.68 20 0 top
NOREF#269  -  []  129.07 149 0 top
NOREF#270  -  []  148.68 20 0 top
NOREF#271  -  []  154.52 114.68 90 top
NOREF#272  -  []  152.05 114.53 0 top
NOREF#273  -  [unnamed#2]  25.65 6.18 180 bottom
NOREF#274  -  [unnamed#2]  176.29 141.22 180 bottom
NOREF#275  -  [unnamed#2]  21.23 143.78 180 bottom
NOREF#276  -  [unnamed#2]  142.07 26.36 180 bottom
OSC1  25MHZ  [OSC4_FJ2500009]  31.72 38.38 180 top
PC101  270UF  [EC83_248_390S]  190.87 14.26 0 top
PC102  10UF  [C0805_H61]  172.77 12.27 90 top
PC103  10UF  [C0805_H61]  179.78 11.76 180 top
PC104  10UF  [C0805_H61]  179.78 13.67 180 top
PC105  1UF  [C0402]  179.78 15.19 180 top
PC106  4.7UF  [C0402]  183.46 20.16 270 top
PC107  1UF  [C0402]  175.44 20.43 90 top
PC108  0.47UF  [C0402]  183.13 23.93 90 top
PC109  150PF  [C0402]  184.52 18.37 270 top
PC110  100NF  [C0402]  185.29 14.49 270 top
PC112  22UF  [C0805_H57]  182.75 34.65 180 top
PC113  22UF  [C0805_H57]  182.77 36.6 180 bottom
PC114  220UF  [EC56_197_229S]  176.61 34.78 90 top
PC115  330UF  [TAJ_D2E]  178.42 35.76 90 bottom
PC116  330UF  [TAJ_D2E]  178.55 25.73 270 bottom
PC117  100NF  [C0402]  181.65 21.43 0 top
PC118  270UF  [EC83_248_390S]  188.48 5.63 270 top
PC119  220UF  [EC56_197_229S]  170.57 34.79 90 top
PC120  1000PF  [C0402]  184.14 16.71 180 top
PC201  10UF  [C0805_H61]  175.01 12.27 90 top
PC202  10UF  [C0805_H61]  168.45 13.5 180 top
PC203  10UF  [C0805_H61]  168.46 11.5 180 top
PC204  1UF  [C0402]  168.48 15.19 180 top
PC205  4.7UF  [C0402]  172.56 19.42 270 top
PC206  1UF  [C0402]  164.23 20.35 90 top
PC207  0.47UF  [C0402]  172.24 23.61 90 top
PC210  22UF  [C0805_H57]  182.75 34.65 180 bottom
PC211  22UF  [C0805_H57]  182.77 38.53 180 top
PC212  220UF  [EC56_197_229S]  164.51 34.8 90 top
PC213  330UF  [TAJ_D2E]  173.63 25.73 270 bottom
PC214  330UF  [TAJ_D2E]  173.5 35.76 90 bottom
PC215  100NF  [C0402]  170.46 21.42 0 top
PC216  270UF  [EC83_248_390S]  195.95 5.63 270 top
PC301  270UF  [EC83_248_390S]  189.83 21.57 180 top
PC302  10UF  [C0805_H61]  206.61 27.76 0 top
PC304  10UF  [C0805_H61]  203.63 30.16 180 top
PC305  1UF  [C0402]  203.84 31.64 180 top
PC306  4.7UF  [C0402]  207.96 37.39 270 top
PC307  1UF  [C0402]  199.29 37.43 90 top
PC308  0.47UF  [C0402]  207.02 40.58 180 top
PC309  0.01UF  [C0402]  208.04 34.97 0 top
PC310  10PF  [C0402]  208.14 31.35 180 top
PC311  47UF  [C0805_H57]  189.1 46.87 90 top
PC312  47UF  [C0805_H57]  191.33 47.28 90 bottom
PC313  47UF  [C0805_H57]  193.6 46.87 90 top
PC314  47UF  [C0805_H57]  195.43 41.9 270 top
PC315  47UF  [C0805_H57]  191.31 46.87 90 top
PC316  470UF  [TAJ_DXC]  196.66 40.6 270 bottom
PC317  100NF  [C0402]  205.61 38.24 0 top
PC318  470UF  [TAJ_DXC]  191.85 40.21 270 bottom
PC319  470UF  [TAJ_DXC]  201.47 40.68 270 bottom
PC320  470UF  [TAJ_DXC]  187.05 39.98 270 bottom
PC321  470UF  [TAJ_DXC]  199.24 97.77 180 bottom
PC322  10UF  [C0805_H61]  207.16 29.64 0 top
PC601  10UF  [C0805_H61]  191.92 28.14 180 top
PC602  10UF  [C0805_H61]  191.92 26.22 180 top
PC603  10UF  [C0805_H61]  199.95 29.3 90 top
PC604  1UF  [C0402]  193.79 36.08 90 top
PC605  4.7UF  [C0402]  195.33 34.16 270 top
PC606  1UF  [C0402]  187.27 35.05 90 top
PC607  0.47UF  [C0402]  194.18 38.08 180 top
PC610  22UF  [C0805_H57]  182.77 38.53 180 bottom
PC611  22UF  [C0805_H57]  182.77 36.6 180 top
PC612  220UF  [EC56_197_229S]  180.56 42.6 180 top
PC615  100NF  [C0402]  191.92 29.63 180 top
PC701  22UF  [C0603]  17.07 20.07 180 top
PC702  0.1UF  [C0402]  17.25 21.37 180 top
PC703  22UF  [C0603]  19.16 26.66 90 top
PC704  0.1UF  [C0402]  20.43 26.63 90 top
PJ1  SHORT  [SHORT_R0603]  201.96 101.63 180 top
PL101  400NH  [L_HCUVD8095D-102KBQL_8X8]  177.31 26.24 180 top
PL102  80NH  [L_HCBS5265_5-2X5-2]  202.71 6.46 180 top
PL201  400NH  [L_HCUVD8095D-102KBQL_8X8]  167.08 26.24 180 top
PL301  120NH  [L_HCUVE966490D-121]  202.55 44.13 90 top
PL601  400NH  [L_HCUVD8095D-102KBQL_8X8]  188.89 40.28 180 top
PL701  BLM18SN220TN1D  [L0603]  17.05 18.57 0 top
PL702  1UH  [L_MLV-YT12N_2-5X2]  19.69 23.45 90 top
PR101  60.4K  [R0402]  179.88 17.48 0 bottom
PR103  10K  [R0402]  174.67 18.01 180 top
PR104  10K  [R0402]  174.67 19.02 180 top
PR105  15K  [R0402]  179.88 16.47 0 bottom
PR106  10K  [R0402]  181.85 14.57 90 bottom
PR107  10K  [R0402]  174.66 16.99 0 top
PR108  10K  [R0402]  174.66 15.97 0 top
PR109  2.2  [R0402]  173.97 20.81 180 top
PR120  56K  [R0402]  185.57 18.37 270 top
PR121  12.4K  [R0402]  183.47 18.37 90 top
PR122  10K  [R0402]  162.79 17.77 0 top
PR123  30.1K  [R0402]  162.79 16.75 0 top
PR124  0  [R0402]  183.13 22.04 270 top
PR125  0  [R0402]  185.57 16.55 90 top
PR126  0  [R0402]  184.23 15.3 90 top
PR127  0  [R0402]  186.59 16.5 90 top
PR128  0  [R0402]  182.93 15.3 90 top
PR201  60.4K  [R0402]  172.74 16.85 180 top
PR202  15K  [R0402]  172.74 15.84 180 top
PR203  10K  [R0402]  172.55 14.8 180 top
PR204  2.2  [R0402]  162.76 19.95 180 top
PR205  2.2  [R0402]  162.75 18.85 180 top
PR206  0  [R0402]  172.25 21.74 270 top
PR207  56K  [R0402]  173.22 18.25 0 bottom
PR208  12.4K  [R0402]  172.73 17.88 0 top
PR301  60.4K  [R0402]  207.22 32.93 180 top
PR303  10K  [R0402]  198.91 35 180 top
PR304  10K  [R0402]  198.91 36.02 180 top
PR305  34.8K  [R0402]  206.44 31.52 90 top
PR306  3.3  [R0402]  207.53 39.17 270 top
PR307  10K  [R0402]  198.76 32.61 0 top
PR308  10K  [R0402]  199.02 31.59 0 top
PR309  2.2  [R0402]  197.13 35.76 0 top
PR320  9.76K  [R0402]  208.04 33.95 0 top
PR321  18.2K  [R0402]  207.68 35.98 0 top
PR601  60.4K  [R0402]  196.23 31.35 180 top
PR602  15K  [R0402]  196.23 30.33 180 top
PR603  10K  [R0402]  196.23 29.31 180 top
PR604  2.2  [R0402]  186.89 33.58 180 top
PR605  2.2  [R0402]  186.89 32.56 180 top
PR606  0  [R0402]  194.89 36.54 270 top
PR701  10K  [R0402]  20.99 18.48 180 top
PU7  MP2152GTF-18-Z  [SOT563-6_0-5_1-6X1-2XB]  19.69 20.36 270 top
PU101  MPQ8645PGVT-6001-Z  [TQFN25_5X4]  179.17 18.36 270 top
PU201  MPQ8645PGVT-6001-Z  [TQFN25_5X4]  167.97 18.36 270 top
PU301  MPQ8645PGVT-6000-Z  [TQFN25_5X4]  203.12 34.81 270 top
PU601  MPQ8645PGVT-6001-Z  [TQFN25_5X4]  191.51 32.81 270 top
Q9  2N7002KDW  [SOT363XD]  79.5 27.89 270 top
Q10  DMN2400UV-7  [SOT563-6XA]  207.85 104.44 90 top
Q24  DMN2400UV-7  [SOT563-6XA]  109.33 144.21 270 top
Q36  BSS138-7-F  [SOT23_GDSXC]  92.15 38.38 90 top
Q38  BSS138-7-F  [SOT23_GDSXC]  55.6 34.44 90 bottom
Q39  BSS138-7-F  [SOT23_GDSXC]  51.81 34.44 90 bottom
Q40  BSS138-7-F  [SOT23_GDSXC]  59.46 34.44 90 bottom
Q42  BSS138-7-F  [SOT23_GDSXC]  73.8 37.53 90 bottom
Q43  BSS138-7-F  [SOT23_GDSXC]  70.25 37.53 90 bottom
Q44  DMG3415U-7  [SOT23_GDSXC]  2.69 36.2 90 bottom
Q45  DMN601WK-7  [SOT323_GDS_2-15X1-3]  6.07 30.96 90 bottom
Q46  DMG3415U-7  [SOT23_GDSXC]  2.79 30.99 90 bottom
Q47  DMG3415U-7  [SOT23_GDSXC]  9.25 30.94 90 bottom
Q48  DMG3415U-7  [SOT23_GDSXC]  6.3 36.2 90 bottom
Q49  DMN601WK-7  [SOT323_GDS_2-15X1-3]  12.45 30.89 90 bottom
Q50  DMG3415U-7  [SOT23_GDSXC]  4.41 105.58 90 bottom
Q51  DMN601WK-7  [SOT323_GDS_2-15X1-3]  3.63 102.06 90 bottom
Q52  DMG6968U-7  [SOT23_GDSXC]  10.3 4.48 270 bottom
Q53  BSS138-7-F  [SOT23_GDSXC]  10.49 9.28 180 bottom
R3  0  [R0402]  98.15 41.14 90 bottom
R4  0  [R0402]  95.11 36.6 270 bottom
R6  0.002  [R2512_4PXF]  97.6 28.72 180 bottom
R7  10  [R0402]  97.03 31.87 90 bottom
R8  10  [R0402]  98.04 31.87 90 bottom
R9  22  [R0402]  83.38 43.02 90 bottom
R10  22  [R0402]  78.44 43.09 0 bottom
R15  51  [R0402]  13.59 38.42 270 top
R16  4.7K  [R0402]  12.85 26.52 90 top
R17  220  [R0402]  13.89 26.52 270 top
R18  220  [R0402]  14.93 26.54 270 top
R19  10K  [R0402]  15.29 80.54 270 bottom
R20  220  [R0402]  14.27 80.54 270 bottom
R21  10K  [R0402]  13.26 80.54 270 bottom
R22  220  [R0402]  162.81 52.35 180 bottom
R23  10K  [R0402]  158.88 57.12 0 bottom
R24  10K  [R0402]  158.88 56.01 0 bottom
R41  22  [R0402]  60.01 72.33 270 bottom
R42  22  [R0402]  58.73 72.33 270 bottom
R43  22  [R0402]  115.27 42.73 180 bottom
R44  22  [R0402]  115.27 43.79 180 bottom
R47  22  [R0402]  53.77 67.92 270 bottom
R48  22  [R0402]  54.93 67.92 270 bottom
R67  2.2K  [R0402]  19.96 80.11 90 top
R68  2.2K  [R0402]  21.11 80.11 90 top
R69  2.2K  [R0402]  17.7 80.11 90 top
R70  2.2K  [R0402]  18.85 80.11 90 top
R71  2.2K  [R0402]  28.57 76.22 90 top
R72  2.2K  [R0402]  29.72 76.22 90 top
R73  2.2K  [R0402]  26.29 76.22 90 top
R74  2.2K  [R0402]  27.43 76.22 90 top
R75  2.2K  [R0402]  35.89 76.2 90 top
R76  2.2K  [R0402]  37.04 76.2 90 top
R77  2.2K  [R0402]  33.61 76.2 90 top
R78  2.2K  [R0402]  34.75 76.2 90 top
R91  4.7K  [R0402]  24.89 85.75 270 bottom
R92  4.7K  [R0402]  21.74 85.72 270 bottom
R93  4.7K  [R0402]  16.61 85.72 270 bottom
R94  4.7K  [R0402]  17.83 98.86 90 bottom
R95  4.7K  [R0402]  20.88 98.86 90 bottom
R96  4.7K  [R0402]  23.93 98.86 90 bottom
R2774  4.7K  [R0402]  58.41 123.12 270 top
R2777  4.7K  [R0402]  33.55 121.11 270 top
R2780  4.7K  [R0402]  31.7 128.8 180 bottom
R2783  4.7K  [R0402]  58.68 128.32 270 bottom
R2786  4.7K  [R0402]  130.77 128.14 270 bottom
R2789  4.7K  [R0402]  154.7 128.46 270 bottom
R2791  4.7K  [R0402]  69.34 54.13 180 bottom
R2792  4.7K  [R0402]  69.37 53.09 180 bottom
R2793  4.7K  [R0402]  69.37 52.07 180 bottom
R2794  4.7K  [R0402]  62.23 52.2 180 bottom
R2795  4.7K  [R0402]  67.87 50.42 180 bottom
R2796  4.7K  [R0402]  61.49 50.44 180 bottom
R2799  4.7K  [R0402]  19.63 65.33 90 top
R2800  4.7K  [R0402]  18.62 65.33 90 top
R2833  4.7K  [R0402]  25.91 85.75 90 bottom
R2834  4.7K  [R0402]  20.73 85.72 90 bottom
R2835  4.7K  [R0402]  17.63 85.72 90 bottom
R2836  4.7K  [R0402]  16.81 98.86 270 bottom
R2837  4.7K  [R0402]  19.86 98.86 270 bottom
R2838  4.7K  [R0402]  22.91 98.86 270 bottom
R2839  4.7K  [R0402]  45.25 123.01 90 top
R2840  4.7K  [R0402]  22.55 123.08 90 top
R2841  4.7K  [R0402]  46.36 130.24 90 bottom
R2842  4.7K  [R0402]  72.13 119.91 0 bottom
R2843  4.7K  [R0402]  144.01 128.64 0 bottom
R2844  4.7K  [R0402]  168.16 128.14 0 bottom
R2847  100K  [R0402]  12.4 80.16 270 top
R2848  10K  [R0402]  14.45 80.21 90 top
R2849  4.7K  [R0402]  67.46 54.13 180 bottom
R2850  4.7K  [R0402]  67.46 53.09 180 bottom
R2851  4.7K  [R0402]  67.49 52.07 180 bottom
R2852  4.7K  [R0402]  60.4 52.2 180 bottom
R2853  4.7K  [R0402]  66.01 50.42 180 bottom
R2854  4.7K  [R0402]  59.69 50.44 180 bottom
R2864  49.9  [R0402]  14.4 91.59 90 top
R2865  49.9  [R0402]  12.44 91.6 90 top
R2866  49.9  [R0402]  11.33 80.19 270 top
R2867  49.9  [R0402]  13.41 80.19 270 top
R2868  49.9  [R0402]  14.26 97.03 270 top
R2869  49.9  [R0402]  16.13 96.8 270 top
R2875  2.7K  [R0603]  93.62 144.38 270 top
R2885  4.7K  [R0402]  82.63 128.38 270 bottom
R2886  4.7K  [R0402]  96.23 125.36 0 bottom
R2888  4.7K  [R0402]  106.15 128.46 270 bottom
R2889  4.7K  [R0402]  119.82 130.32 0 bottom
R2891  4.7K  [R0402]  104.18 121.1 270 top
R2892  4.7K  [R0402]  93.25 123.01 90 top
R2894  4.7K  [R0402]  81.75 122.82 270 top
R2895  4.7K  [R0402]  69.25 123.01 90 top
R2897  4.7K  [R0402]  153.51 123.07 270 top
R2898  4.7K  [R0402]  141.25 123.01 90 top
R2900  4.7K  [R0402]  129.76 122.85 270 top
R2901  4.7K  [R0402]  117.37 123.14 90 top
R2910  0  [R0201]  192.71 90.2 0 bottom
R2916  2.2  [R0603]  69.8 66.21 180 bottom
R2917  2.2  [R0603]  65.73 67.5 270 bottom
R2918  4.7K  [R0402]  181.88 127.91 0 top
R2919  4.7K  [R0402]  172.62 124.28 180 top
R2920  4.7K  [R0402]  172.62 120.22 180 top
R2921  4.7K  [R0402]  185.7 121.36 0 top
R2922  4.7K  [R0402]  186.72 124.41 0 top
R2923  4.7K  [R0402]  181.88 126.89 180 top
R2924  4.7K  [R0402]  186.72 126.44 0 top
R2925  4.7K  [R0402]  173.08 125.17 0 bottom
R2926  4.7K  [R0402]  172.62 121.23 0 top
R2927  4.7K  [R0402]  185.7 122.38 180 top
R2928  4.7K  [R0402]  188.75 124.41 180 top
R2929  4.7K  [R0402]  188.75 126.44 180 top
R2930  4.7K  [R0402]  72.54 64.44 270 bottom
R2931  4.7K  [R0402]  72.54 62.61 90 bottom
R2932  4.7K  [R0402]  72.62 60.38 270 bottom
R2933  4.7K  [R0402]  72.59 58.57 90 bottom
R2934  4.7K  [R0402]  72.54 56.46 270 bottom
R2935  4.7K  [R0402]  72.54 54.69 90 bottom
R2936  4.7K  [R0402]  71.5 64.44 90 bottom
R2937  4.7K  [R0402]  71.5 62.61 270 bottom
R2938  4.7K  [R0402]  71.55 60.38 90 bottom
R2939  4.7K  [R0402]  71.55 58.57 270 bottom
R2940  4.7K  [R0402]  71.53 56.46 90 bottom
R2941  4.7K  [R0402]  71.5 54.69 270 bottom
R2949  49.9  [R0402]  15.54 109.7 90 top
R2950  49.9  [R0402]  14.25 109.7 90 top
R2951  49.9  [R0402]  180.03 144.17 180 top
R2952  49.9  [R0402]  180.69 140.36 270 top
R2953  49.9  [R0402]  183.24 138.96 180 top
R2954  49.9  [R0402]  190.64 143.6 0 top
R2958  22  [R0402]  59.69 69.9 270 top
R2959  22  [R0402]  58.67 69.88 270 top
R2960  100K  [R0402]  64.95 71.78 270 top
R2961  150  [R0402]  64.95 69.95 90 top
R2963  1K  [R0201]  61.77 69.77 270 top
R2964  4.75K  [R0402]  67.01 69.95 270 top
R2966  4.75K  [R0402]  65.99 69.95 270 top
R2967  4.75K  [R0402]  67.01 71.78 270 top
R2968  4.75K  [R0402]  65.99 71.78 270 top
R2969  1K  [R0402]  60.76 69.9 90 top
R2970  1K  [R0201]  56.62 69.77 270 top
R2971  1K  [R0402]  57.63 69.88 90 top
R3004  0  [R0201]  191.21 86.53 0 bottom
R3005  0  [R0201]  194.52 71.15 0 bottom
R3043  4.7K  [R0402]  71.81 19.04 90 top
R3044  22  [R0402]  71.81 21.15 270 top
R3045  22  [R0402]  70.8 21.15 270 top
R3046  4.7K  [R0402]  99.19 41.15 270 bottom
R3047  4.7K  [R0402]  70.8 19.04 90 top
R3048  100  [R0402]  82.22 18.54 0 top
R3049  10K  [R0402]  69.76 19.04 270 top
R3050  33  [R0402]  69.76 21.27 270 top
R3051  16K  [R0402]  68.7 19.01 270 top
R3052  4.7K  [R0402]  67.68 19.01 90 top
R3053  33  [R0402]  59.72 19.13 90 top
R3054  33  [R0402]  66.85 26.95 0 top
R3055  4.7K  [R0402]  76.66 27.1 180 top
R3063  2.2K  [R0402]  22.35 38.81 90 top
R3064  2.2K  [R0402]  23.44 38.81 90 top
R3065  2.2K  [R0402]  20.12 38.84 90 top
R3066  2.2K  [R0402]  21.23 38.84 90 top
R3067  2.2K  [R0402]  43.48 76.2 90 top
R3068  2.2K  [R0402]  44.63 76.2 90 top
R3069  2.2K  [R0402]  41.2 76.2 90 top
R3070  2.2K  [R0402]  42.34 76.2 90 top
R3071  2.2K  [R0402]  28.09 95.43 90 top
R3072  2.2K  [R0402]  29.24 95.43 90 top
R3073  2.2K  [R0402]  25.81 95.43 90 top
R3074  2.2K  [R0402]  26.95 95.43 90 top
R3098  100  [R0402]  194.13 77.1 0 bottom
R3099  33  [R0402]  65.5 19.01 90 top
R3100  33  [R0402]  66.52 19.01 90 top
R3101  470  [R0402]  204.79 76.02 180 top
R3102  56.2  [R0402]  204.79 75 0 bottom
R3103  470  [R0402]  204.79 75 180 top
R3104  56.2  [R0402]  204.79 76.02 0 bottom
R3121  100  [R0402]  160.9 12.82 180 bottom
R3123  100K  [R0402]  196.11 12.01 180 bottom
R3124  100K  [R0402]  196.13 9.54 0 bottom
R3125  1K  [R0402]  185.55 116.87 180 top
R3126  1K  [R0402]  172.62 115.01 0 top
R3127  1K  [R0402]  172.62 116.03 0 top
R3128  1K  [R0402]  172.62 119.08 0 top
R3129  1K  [R0402]  185.55 115.85 0 top
R3130  1K  [R0402]  172.62 114 180 top
R3131  1K  [R0402]  172.62 117.04 180 top
R3132  1K  [R0402]  172.62 118.06 180 top
R3136  4.7K  [R0402]  208.02 83.38 0 top
R3137  4.7K  [R0402]  208.03 82.31 0 top
R3138  4.7K  [R0402]  208.02 84.45 0 top
R3139  4.7K  [R0402]  208.03 80.25 0 top
R3140  4.7K  [R0402]  208.02 86.53 0 top
R3141  4.7K  [R0402]  208.02 87.56 0 top
R3142  4.7K  [R0402]  208.02 85.51 0 top
R3143  4.7K  [R0402]  208.03 81.29 0 top
R3144  4.7K  [R0402]  208.05 78.13 0 top
R3145  4.7K  [R0402]  208.02 77.06 0 top
R3146  4.7K  [R0402]  208.03 79.18 0 top
R3147  4.75K  [R0402]  206.46 66.33 90 top
R3148  4.7K  [R0402]  78.69 31.72 90 top
R3149  4.75K  [R0402]  206.46 64.53 90 top
R3150  4.7K  [R0402]  205.94 79.18 0 top
R3151  4.7K  [R0402]  205.92 77.06 0 top
R3152  4.7K  [R0402]  205.95 78.13 0 top
R3153  4.7K  [R0402]  205.94 81.29 0 top
R3154  4.7K  [R0402]  205.92 85.51 0 top
R3155  4.7K  [R0402]  205.92 86.53 0 top
R3156  4.7K  [R0402]  205.94 80.25 0 top
R3157  4.7K  [R0402]  205.95 84.45 0 top
R3158  4.7K  [R0402]  205.94 82.31 0 top
R3159  4.7K  [R0402]  205.95 83.38 0 top
R3160  4.7K  [R0402]  205.92 87.56 0 top
R3161  1K  [R0402]  199.23 93.01 270 bottom
R3162  1K  [R0402]  203.17 78.26 180 bottom
R3187  27  [R0402]  54.59 66.21 180 top
R3188  27  [R0402]  54.59 64.94 180 top
R3189  27  [R0402]  54.59 63.41 180 top
R3190  27  [R0402]  54.59 62.14 180 top
R3191  27  [R0402]  54.59 60.62 180 top
R3192  27  [R0402]  54.59 59.35 180 top
R3193  27  [R0402]  54.59 57.82 180 top
R3194  27  [R0402]  54.59 56.55 180 top
R3195  27  [R0402]  58.35 52.46 270 top
R3196  27  [R0402]  59.62 52.46 270 top
R3197  27  [R0402]  61.4 52.46 270 top
R3198  27  [R0402]  62.67 52.46 270 top
R3199  27  [R0402]  64.32 52.46 270 top
R3200  27  [R0402]  65.59 52.46 270 top
R3201  27  [R0402]  67.12 52.46 270 top
R3202  27  [R0402]  68.39 52.46 270 top
R3203  27  [R0402]  74.14 56.06 0 top
R3204  27  [R0402]  74.14 57.33 0 top
